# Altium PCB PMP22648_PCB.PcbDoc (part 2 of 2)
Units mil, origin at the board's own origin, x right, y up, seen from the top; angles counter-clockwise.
Board outline 3299.21 x 2751.97 mil, 6 copper layers (Top Layer, GND, GND (Mid2), Signal Layer 3, GND (Mid4), Bottom Layer), stack 107.669 mil thick; 130 components, 60 nets, 290 pads, 212 vias.
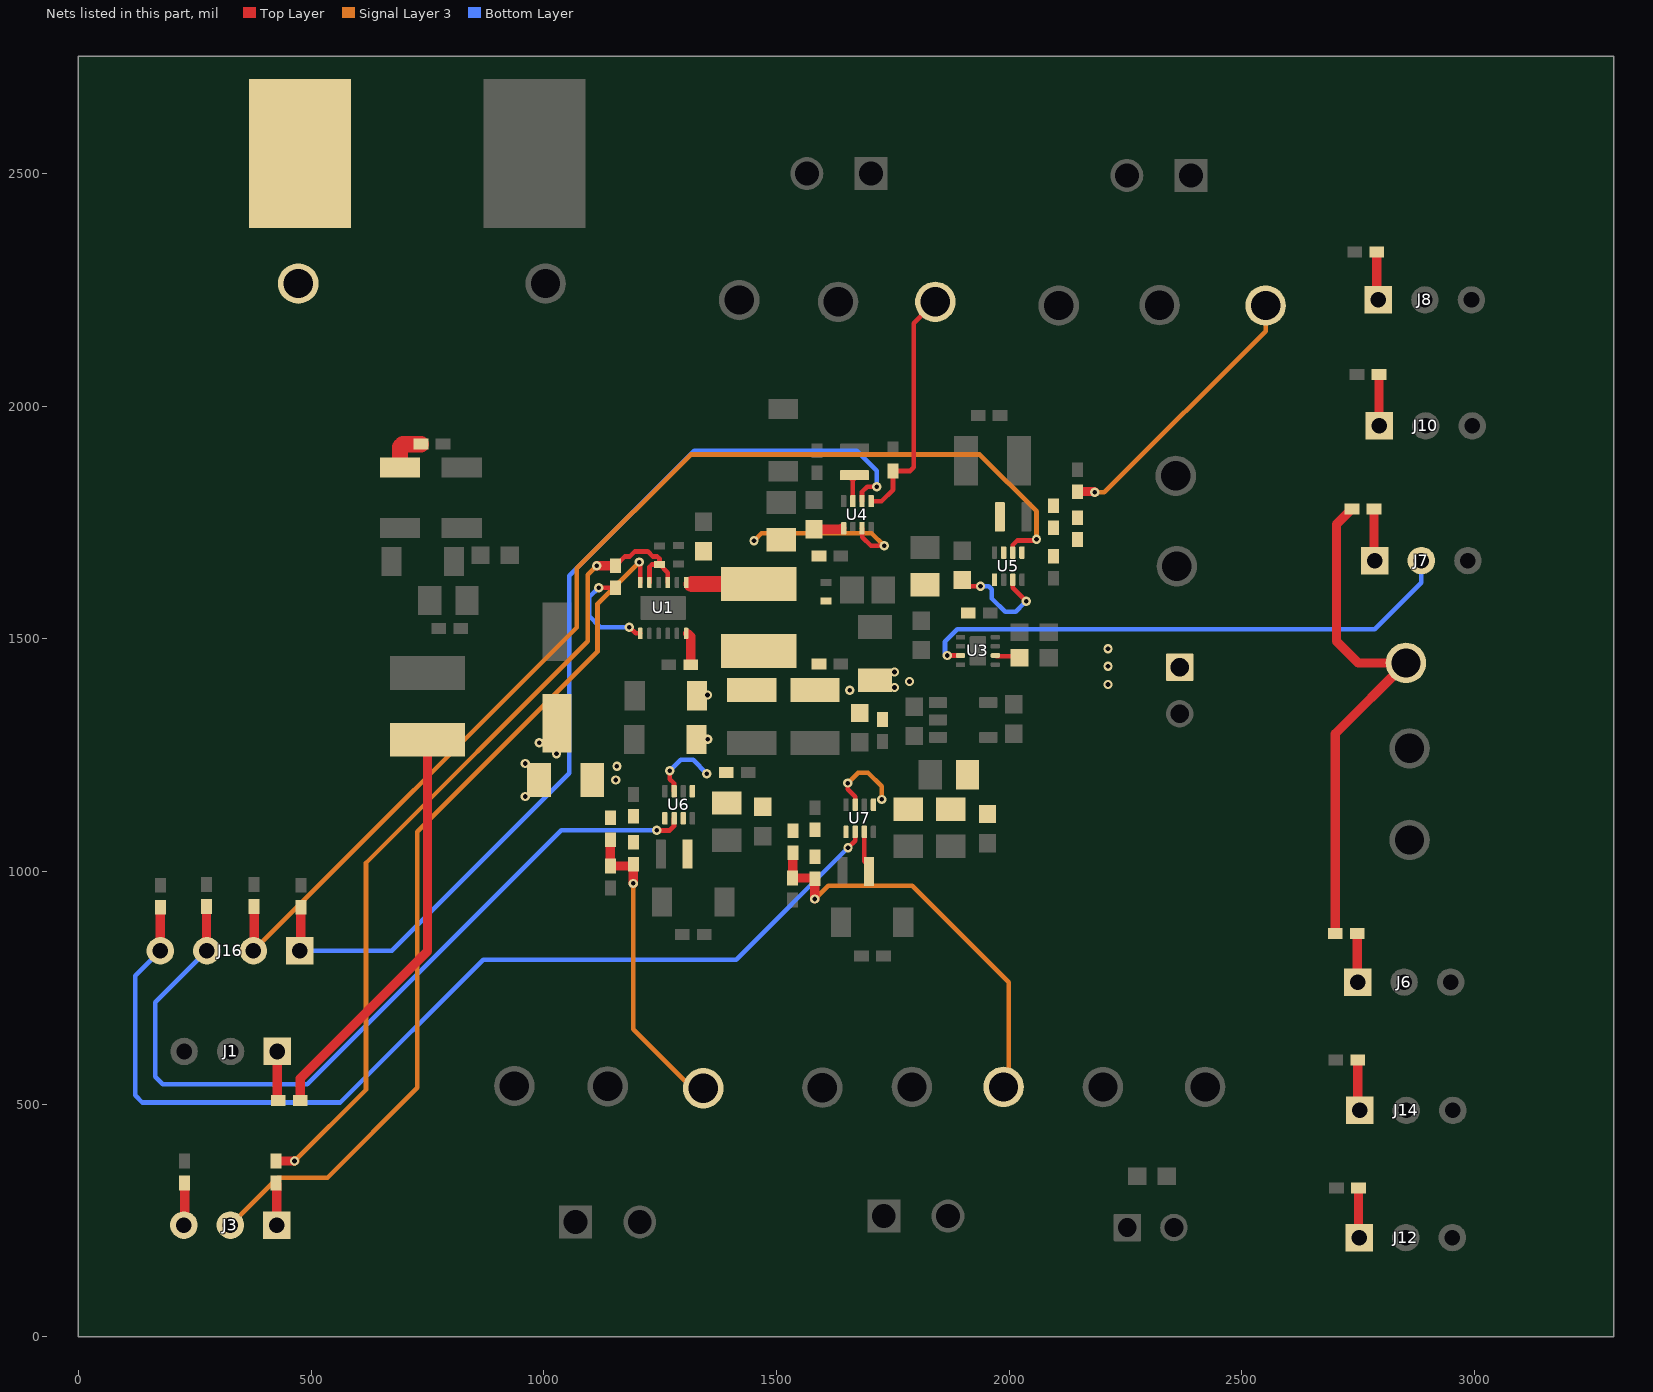
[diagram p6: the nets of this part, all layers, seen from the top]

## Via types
v1: diameter 20, hole 10, Top Layer to Bottom Layer, 207 vias
v2: diameter 19.68, hole 7.87, Top Layer to Bottom Layer, 5 vias

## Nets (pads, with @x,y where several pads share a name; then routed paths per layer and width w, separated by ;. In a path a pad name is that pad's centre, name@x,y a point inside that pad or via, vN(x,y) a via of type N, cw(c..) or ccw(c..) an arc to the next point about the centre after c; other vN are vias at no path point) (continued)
NetC19_1: C19.1 C22.1 R14.2 U4.1 U4.3 | length 432.3
  Top Layer w10: U4.3@1683.99,1737.97 1684.89,1737.07 1684.89,1718.61 1703.37,1700.13 v1(1731.6,1700.13)
  Top Layer w20: C22.1@1580.81,1735.61 1638.16,1735.61 U4.1@1640.52,1737.97
  Signal Layer 3 w10: v1(1452.03,1711.32) 1468.03,1727.32 1704.41,1727.32 v1(1731.6,1700.13)
NetC21_1: C21.1 C27.1 R18.2 U5.1 U5.3 | length 244.7
  Top Layer w10: C27.1@1899.82,1626.78 1913.6,1613 v1(1938.75,1613) ; U5.3@2008.09,1627.17 2008.09,1610.47 v1(2037.21,1581.35)
  Bottom Layer w10: v1(1938.75,1613) 1956.68,1613 1963.11,1606.56 1963.11,1586.92 1991.56,1558.48 2014.34,1558.48 2016.5,1560.64 2016.5,1560.96 2029.9,1574.36 2030.22,1574.36 v1(2037.21,1581.35)
NetC23_1: C23.1 U3.6 | length 55.8
  Top Layer w10: U3.6@1970.47,1464.41 1972.28,1462.6 2022.3,1462.6 C23.1@2022.3,1459.38
NetC25_1: C25.1 C33.1 R24.2 U6.1 U6.3 | length 149.4
  Top Layer w10: v1(1270.58,1216.54) 1270.58,1198.92 1280.14,1189.36 U6.3@1280.14,1172.88
  Bottom Layer w10: v1(1270.58,1216.54) 1294.2,1240.16 1320.9,1240.16 v1(1350.39,1210.66)
NetC29_1: C29.1 C31.1 C38.1 R30.2 U7.1 U7.3 | length 175.5
  Top Layer w10: v1(1653.2,1190.27) 1653.2,1176.8 1669.29,1160.71 U7.3@1669.29,1143.75
  Signal Layer 3 w10: v1(1653.2,1190.27) 1653.27,1190.27 1675.47,1212.47 1696.86,1212.47 1726.27,1183.07 v1(1726.27,1155.18)
NetC30_1: C30.1 R19.1 R22.2 TP7.1 | length 603.9
  Top Layer w20: R19.1@2146.7,1816.68 2182.54,1816.68 v1(2184.26,1814.96)
  Signal Layer 3 w10: v1(2184.26,1814.96) 2204.72,1814.96 2551.31,2161.54 TP7.1@2551.31,2216.54
NetC30_2: C30.2 R22.1 R23.2 U5.5
NetC36_1: C36.1 R25.1 R28.2 TP10.1 | length 664.6
  Top Layer w20: C36.1@1143.07,1068.21 R25.1@1143.07,1012.11 1188.86,1012.11 R28.2@1192.54,1015.8 v1(1192.54,974.71)
  Signal Layer 3 w10: v1(1192.54,974.71) 1192.54,660.95 1318.9,534.59 TP10.1@1342.8,534.59
NetC36_2: C36.2 R28.1 R29.2 U6.5
NetC42_1: C42.1 R31.1 R34.2 TP13.1 | length 889.9
  Top Layer w10: R31.1@1535.15,986.36 R31.1@1535.24,986.46
  Top Layer w20: R31.1@1535.15,986.36 1580.85,986.36 R34.2@1582.67,984.53 v1(1582.68,941.08) ; R31.1@1535.24,986.46 C42.1@1535.24,1040.33
  Signal Layer 3 w10: v1(1582.68,941.08) 1611.41,969.82 1791.77,969.82 1999.55,762.04 1999.55,548.76 TP13.1@1988.19,537.4
NetC42_2: C42.2 R34.1 R35.2 U7.5
NetJ1_1: J1.1 R2.1 | length 106.3
  Top Layer w20: J1.1@427.16,613.55 427.16,510.6 R2.1@429.52,508.23
NetJ3_1: J3.1 R6.2 | length 91.3
  Top Layer w20: R6.2@425.2,331.04 426.69,329.55 J3.1@426.69,240.33
NetJ3_3: J3.3 R7.2 | length 91.4
  Top Layer w20: J3.3@226.69,240.33 228.35,241.99 R7.2@228.35,331.04
NetJ6_1: J6.1 R9.2 | length 104.8
  Top Layer w20: R9.2@2748.03,867.09 2748.03,763.56 J6.1@2748.93,762.65
NetJ7_1: J7.1 R13.2 | length 111.9
  Top Layer w20: R13.2@2784.17,1779.53 2784.17,1670.12 J7.1@2785.94,1668.34
NetJ8_1: J8.1 R15.2 | length 104.7
  Top Layer w20: R15.2@2790.25,2331.81 2790.25,2231.9 J8.1@2793.65,2228.51
NetJ10_1: J10.1 R20.2 | length 110.5
  Top Layer w20: R20.2@2794.82,2068.08 2794.82,1958.29 J10.1@2795.32,1957.78
NetJ12_1: J12.1 R26.2 | length 107.3
  Top Layer w20: R26.2@2750.82,320.23 2750.82,215.46 J12.1@2752.59,213.69
NetJ14_1: J14.1 R32.2 | length 110.5
  Top Layer w20: R32.2@2749.04,595.59 2749.04,491.55 J14.1@2753.64,486.95
NetL5_1: L5.1 U4.7 | length 57.2
  Top Layer w10: U4.7@1664.3,1796.24 L5.1@1664.3,1848.18
  Top Layer w20: L5.1@1664.3,1848.18 L5.1@1668.06,1851.93
NetL6_1: L6.1 U5.7
NetL7_1: L7.1 U6.7
NetL8_1: L8.1 U7.7 | length 75.9
  Top Layer w10: U7.7@1688.97,1085.48 1688.97,1022.1 L8.1@1697.83,1013.24
NetR16_1: R16.1 TP5.1 U4.5 | length 519.5
  Top Layer w10: U4.5@1703.67,1796.24 1725.92,1796.24 1750.74,1821.06 R16.1@1750.74,1860.79 1786.97,1860.79 1795.28,1869.09 1795.28,2178.14 TP5.1@1841.54,2224.41
ON_LS: J7.2 U3.3 | length 1184
  Top Layer w10: v1(1866.91,1464.49) U3.3@1895.67,1464.49
  Bottom Layer w10: v1(1866.91,1464.49) 1862.2,1469.19 1862.2,1493.85 1888.86,1520.51 2785.8,1520.51 2885.94,1620.65 J7.2@2885.94,1668.34
PG_1V8: J16.1 R17.1 U4.6 | length 2135.5
  Top Layer w10: J16.1@476.17,829.94 J16.1@478.15,831.91 ; U4.6@1683.99,1796.24 1683.99,1816.07 1695.01,1827.09 v1(1715.85,1827.09)
  Top Layer w20: J16.1@478.15,831.91 R17.1@478.15,923.23
  Bottom Layer w10: J16.1@476.17,829.94 673.92,829.94 1055.12,1211.13 1055.12,1635.72 1323.5,1904.1 1672.75,1904.1 1715.85,1861 v1(1715.85,1827.09)
PG_1V35: J16.3 R27.1 U6.6 | length 1780
  Top Layer w10: J16.3@275.59,830.52 J16.3@276.17,829.94 ; v1(1243.02,1088.63) 1243.1,1088.55 1270.55,1088.55 1280.14,1098.14 U6.6@1280.14,1114.62
  Top Layer w20: J16.3@275.59,830.52 R27.1@275.59,925.2
  Bottom Layer w10: J16.3@276.17,829.94 165.35,719.12 165.35,559.06 181.1,543.31 492.13,543.31 1037.45,1088.63 v1(1243.02,1088.63)
PG_1V175: J16.4 R33.1 U7.6 | length 2231.9
  Top Layer w10: v1(1653.96,1051.23) 1669.29,1066.55 U7.6@1669.29,1085.48
  Top Layer w20: J16.4@176.17,829.94 176.17,922.72 R33.1@176.69,923.23
  Bottom Layer w10: J16.4@176.17,829.94 122.05,775.81 122.05,519.69 137.8,503.94 562.99,503.94 870.08,811.02 1413.76,811.02 v1(1653.96,1051.23)
PG_3V3_Buck: J16.2 R21.1 U5.6 | length 2477.7
  Top Layer w10: U5.6@2008.09,1685.44 2008.09,1701.92 2017.68,1711.5 2056.01,1711.5 v1(2059.06,1714.55)
  Top Layer w20: J16.2@376.17,829.94 377.95,831.72 R21.1@377.95,925.2
  Signal Layer 3 w10: J16.2@376.17,829.94 1070.87,1524.63 1070.87,1651.47 1315.62,1896.22 1937.04,1896.22 2059.06,1774.21 v1(2059.06,1714.55)
RES: R8.1 U1.7 | length 230.9
  Top Layer w10: v1(1118.04,1610.24) 1118.35,1609.93 R8.1@1154.43,1609.93 ; v1(1184.04,1525.35) 1197.5,1511.9 U1.7@1207.58,1511.9
  Bottom Layer w10: v1(1118.04,1610.24) 1097.92,1590.12 1097.92,1549.31 1121.88,1525.35 v1(1184.04,1525.35)
SW_5V: C1.2 C4.2 L3.1 U1.1 | length 148.7
  Top Layer w35: 1318.31,1618 L3.1@1462.23,1618 L3.1@1458.88,1621.35
SYNC: J3.2 U1.6 | length 1895.9
  Top Layer w10: v1(1205.61,1665.17) 1207.58,1663.2 U1.6@1207.58,1621.35
  Signal Layer 3 w10: J3.2@326.69,240.33 428.87,342.52 535.43,342.52 728.35,535.43 728.35,1085.77 1115.74,1473.16 1115.74,1575.29 v1(1205.61,1665.17)
VBAT: C5.1 J2.1 L2.1 VBAT.1 | length 91.7
  Top Layer w35: L2.1@691.03,1868.41 691.03,1912.38 697.08,1918.43 C5.1@736.24,1918.43
VCC: C14.1 R6.1 R8.2 U1.3 U1.5 | length 1857.4
  Top Layer w10: v1(1114.17,1657.48) v1@1114.48,1657.17 ; R8.2@1154.43,1657.17 1174.43,1677.17 1185.26,1677.17 1196.13,1688.04 1223.19,1688.04 1234.06,1677.17 1243.94,1677.17 1248.92,1672.18 C14.1@1248.92,1660.01 ; U1.5@1227.26,1621.35 1227.26,1654.61 1232.66,1660.01 C14.1@1248.92,1660.01 ; U1.3@1266.63,1621.35 1266.63,1642.3 C14.1@1248.92,1660.01
  Top Layer w20: R6.1@425.2,378.29 v1(464.57,378.29) ; v1@1114.48,1657.17 R8.2@1154.43,1657.17
  Signal Layer 3 w10: v1@464.9,378.29 618.11,531.5 618.11,1018.62 1094.49,1495 1094.49,1637.8 v1(1114.17,1657.48)
  Signal Layer 3 w20: v1(464.57,378.29) v1@464.9,378.29
VIN_5V: C7.1 C9.1 C10.1 R10.2 U1.12 | length 70.1
  Top Layer w20: U1.12@1309.11,1511.9 1315.85,1505.16 C10.1@1315.85,1444.57
  other v1: 1155.06,1196.85 1157.33,1226.6 1352.34,1284.81 1351.94,1379.52
VIN_FILT: C8.1 L1.2 R2.2 R10.1 | length 888.4
  Top Layer w20: R2.2@476.77,508.23 476.77,555.51 750.34,829.08 L1.2@750.34,1283.36
  other v1: 960.63,1161.42 960.63,1232.21 1027.56,1253.02 990.16,1277
VSYS_5V: C11.1 C12.1 C17.1 J4.1 L3.2 R5.2 R9.1 R11.1 R12.1 R13.1 TP2.1 | length 1110.8
  Top Layer w20: R9.1@2700.79,867.09 2700.79,1296.41 TP2.1@2852.78,1448.41 2750.51,1448.41 2703.77,1495.15 2703.77,1746.37 R13.1@2736.92,1779.53
  other v1: 1657.88,1389.76 1753.67,1395.68 2212.6,1402.28 1786.07,1408.6 1753.67,1428.92 2212.6,1441.58 2212.6,1479.03
pads on no net: U3.0

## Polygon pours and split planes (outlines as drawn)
NetC13_1 on Top Layer "TOP_LAYER_NETC13_1_P110" (solid, remove dead copper, pour order 110): 1773.69,1379.52 1862.2,1379.52 1862.2,1350.39 1860.71,1350.39 1818.61,1350.39 1818.61,1330.71 1773.69,1330.71
GND on Top Layer "TOP_LAYER_GND_P108" (solid, remove dead copper, pour order 108): 1330.71,2751.97 1330.71,2145.67 2240.16,2145.67 2244.09,2141.73 2244.09,732.28 886.14,732.28 887.37,733.51 887.37,1203.27 615.62,1203.27 614.17,1204.72 614.17,1416.43 475.31,1416.43 476.61,1417.72 476.61,1849.65 118.11,1849.65 118.11,2751.97
3.3V_LDO on Top Layer "TOP_LAYER_3.3V_LDO_P106" (solid, remove dead copper, pour order 106): 1944.73,1381.72 1944.09,1381.09 1944.09,1339.68 2027.96,1339.68 2029.06,1338.58 2029.9,1339.42 2029.9,1381.57
VIN_5V on Top Layer "TOP_LAYER_VIN_5V_P088" (solid, remove dead copper, pour order 88): 1075.08,1242.2 1074.8,1150.59 1164.87,1150.59 1169.29,1150.59 1169.29,1243.53
NetC21_1 on Top Layer "TOP_LAYER_NETC21_1_P062" (solid, remove dead copper, pour order 62): 1779.19,1582.31 1885.46,1582.31 1885.83,1582.68 1886.47,1582.03 1886.47,1543.31 1928.42,1543.31 1929.13,1544.02 1928.36,1544.79 1928.36,1604.03 1963.11,1604.03 1974.22,1615.13 1974.22,1640.5 1929.59,1640.5 1929.59,1649.61 1779.19,1649.61
NetC30_2 on Top Layer "TOP_LAYER_NETC30_2_P060" (solid, remove dead copper, pour order 60): 2021.67,1673.23 2073.86,1673.23 2073.86,1657.48 2118.11,1657.17 2118.11,1688.04 2117.17,1688.98 2167.2,1689.19 2167.2,1731.13 2165.35,1732.28 2117.17,1732.28 2117.17,1755.91 2073.86,1755.91 2073.86,1696.85 2073.32,1696.31 2022.3,1696.31
NetC19_1 on Top Layer "TOP_LAYER_NETC19_1_P058" (solid, remove dead copper, pour order 58): 1437.59,1753.5 1437.41,1679.33 1550.58,1679.33 1552.26,1681.01 1552.26,1706.08 1567.06,1706.08 1567.06,1666.09 1610.24,1666.09 1609.35,1723.41 1649.54,1723.41 1648.93,1724.02 1648.93,1753.5
NetC16_1 on Top Layer "TOP_LAYER_NETC16_1_P056" (solid, remove dead copper, pour order 56): 1673.23,1565.84 1673.23,1444.84 1782.48,1444.92 1782.48,1434.35 1783.83,1432.99 1905.51,1432.99 1905.09,1447.59 1900.09,1447.59 1838.22,1447.59 1838.22,1481.54 1907.5,1481.54 1907.5,1511.27 1903.03,1515.75 1832.6,1515.75 1760.41,1515.75 1760.41,1565.84
VSYS_5V on Top Layer "TOP_LAYER_VSYS_5V_P052" (solid, remove dead copper, pour order 52): 1361.83,1527.56 1568.25,1527.56 1568.25,1467.45 1610.24,1467.41 1610.24,1424.11 1664.28,1424.11 1664.28,1444.88 1795.28,1444.88 1795.28,1370.37 1751.87,1370.37 1751.87,1309.34 1750.19,1311.02 1651.48,1311.02 1651.48,1342.89 1651.93,1343.34 1651.48,1343.79 1361.83,1343.79
NetC29_1 on Top Layer "TOP_LAYER_NETC29_1_P050" (solid, remove dead copper, pour order 50): 1700.79,1168.3 1743.46,1168.3 1875,1168.3 1874.02,1169.28 1874.02,1248.35 1944.85,1248.35 1944.88,1153.35 1979.96,1153.35 1982.28,1151.04 1982.28,1102.36 1743.46,1102.36 1743.46,1134.3 1742.09,1132.92 1700.79,1132.92
NetC36_2 on Top Layer "TOP_LAYER_NETC36_2_P048" (solid, remove dead copper, pour order 48): 1122.57,1139.84 1123.93,1138.47 1266.63,1138.47 1266.63,1107.64 1265.29,1106.3 1214.2,1106.3 1214.2,1043.31 1213.51,1042.62 1164.72,1042.62 1164.72,1094.49 1121.41,1094.49
NetC25_1 on Top Layer "TOP_LAYER_NETC25_1_P044" (solid, remove dead copper, pour order 44): 1310.57,1189.6 1340.23,1189.6 1340.23,1234.3 1417.32,1234.3 1417.32,1181.33 1498.77,1181.33 1499.27,1180.83 1499.27,1114.17 1353.33,1114.17 1353.33,1157.48 1310.6,1157.48
VIN_FILT on Top Layer "TOP_LAYER_VIN_FILT_P042" (solid, remove dead copper, pour order 42): 649.97,1355.21 650.85,1354.33 893.7,1354.33 893.7,1387.65 896.9,1390.85 897.98,1389.76 1162.31,1389.76 1162.31,1243.11 1039.37,1243.11 1039.37,1150.91 824.31,1150.62 824.31,1224.41 646.01,1224.41
NetC42_2 on Top Layer "TOP_LAYER_NETC42_2_P032" (solid, remove dead copper, pour order 32): 1514.74,1111.95 1518.72,1107.98 1656.21,1107.98 1656.21,1064.42 1604.33,1064.25 1604.33,1008.15 1556.8,1007.87 1556.8,1070.77 1513.59,1070.87
NetL8_1 on Top Layer "TOP_LAYER_NETL8_1_P030" (solid, remove dead copper, pour order 30): 1681.55,1092.65 1681.55,958.96 1713.58,958.96 1713.58,1035.42 1700.79,1035.44 1700.79,1092.56
5V_LS on Top Layer "TOP_LAYER_5V_LS_P024" (solid, remove dead copper, pour order 24): 1935.69,1577.68 1935.69,1534.37 1952.76,1534.37 1952.76,1478.27 1988.59,1478.27 1992.77,1474.09 1993.81,1475.13 1993.81,1487.64 2062.79,1487.64 2063.19,1565.54 2017.25,1565.54 1984.9,1533.19 1984.9,1576.79
NetC30_1 on Top Layer "TOP_LAYER_NETC30_1_P022" (solid, remove dead copper, pour order 22): 2073.86,1811.76 2073.86,1763.78 2124.6,1763.78 2126.2,1762.19 2125.04,1761.03 2125.04,1732.28 2168.35,1732.28 2168.35,1834.65 2125.04,1834.65 2125.04,1811.02
VIN_5V on Top Layer "TOP_LAYER_VIN_5V_P010" (solid, remove dead copper, pour order 10): 1275.43,1557.75 1275.22,1236.22 1356.91,1236.22 1356.91,1425.2 1341.35,1425.2 1340.23,1424.07 1338.58,1425.72 1338.58,1558.54
SW_5V on Top Layer "TOP_LAYER_SW_5V_P006" (solid, remove dead copper, pour order 6): 1295.28,1645.37 1314.96,1645.37 1314.87,1712.6 1371.95,1712.6 1370.68,1711.32 1370.68,1660.18 1623.95,1660.18 1623.95,1570.87 1566.56,1570.87 1357.9,1570.87 1357.9,1606.3 1294.54,1605.36
GND on Bottom Layer "BOTTOM_LAYER_GND_P098" (solid, remove dead copper, pour order 98): 1330.71,2751.97 1330.71,2145.67 2240.16,2145.67 2244.09,2141.73 2244.09,732.28 886.14,732.28 887.37,733.51 887.37,1203.27 615.62,1203.27 614.17,1204.72 614.17,1416.43 475.31,1416.43 476.61,1417.72 476.61,1849.65 118.11,1849.65 118.11,2751.97
VSYS_5V on Bottom Layer "BOTTOM_LAYER_VSYS_5V_P068" (solid, remove dead copper, pour order 68): 1361.83,1531.5 2228.35,1531.5 2228.35,1377.64 1646.32,1377.64 1646.01,1342.52 1363.11,1342.52 1361.83,1343.79
GND on Signal Layer 3 "SIGNAL_LAYER_3_GND_P094" (solid, remove dead copper, pour order 94): 1330.71,2751.97 1330.71,2145.67 2240.16,2145.67 2244.09,2141.73 2244.09,732.28 886.14,732.28 887.37,733.51 887.37,1203.27 615.62,1203.27 614.17,1204.72 614.17,1416.43 475.31,1416.43 476.61,1417.72 476.61,1849.65 118.11,1849.65 118.11,2751.97
VIN_5V on Signal Layer 3 "SIGNAL_LAYER_3_VIN_5V_P072" (solid, remove dead copper, pour order 72): 1288.28,1523.62 1184.04,1397.18 1075.15,1263.78 1074.8,1150.59 1160.16,1150.59 1161.15,1149.61 1161.15,1194.76 1251.97,1194.76 1251.97,1228.35 1384.2,1228.35 1384.2,1523.62
5V_LS on Signal Layer 3 "SIGNAL_LAYER_3_5V_LS_P070" (solid, remove dead copper, pour order 70): 1417.32,1692 1417.32,1165.98 1858.27,1165.98 1858.27,1468.26 2075.02,1468.26 2075.02,1686.27
GND on GND "GND_GND_P092" (solid, remove dead copper, pour order 92): 1330.71,2751.97 1330.71,2145.67 2240.16,2145.67 2244.09,2141.73 2244.09,732.28 886.14,732.28 887.37,733.51 887.37,1203.27 615.62,1203.27 614.17,1204.72 614.17,1416.43 475.31,1416.43 476.61,1417.72 476.61,1849.65 118.11,1849.65 118.11,2751.97
GND on GND (Mid2) "GND_GND_P100" (solid, remove dead copper, pour order 100): 1330.71,2751.97 1330.71,2145.67 2240.16,2145.67 2244.09,2141.73 2244.09,732.28 886.14,732.28 887.37,733.51 887.37,1203.27 615.62,1203.27 614.17,1204.72 614.17,1416.43 475.31,1416.43 476.61,1417.72 476.61,1849.65 118.11,1849.65 118.11,2751.97
GND on GND (Mid4) "GND_GND_P096" (solid, remove dead copper, pour order 96): 1330.71,2751.97 1330.71,2145.67 2240.16,2145.67 2244.09,2141.73 2244.09,732.28 886.14,732.28 887.37,733.51 887.37,1203.27 615.62,1203.27 614.17,1204.72 614.17,1416.43 475.31,1416.43 476.61,1417.72 476.61,1849.65 118.11,1849.65 118.11,2751.97

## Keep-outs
Keep-Out Layer:
  text ".Layer_Name" at 577,-858.49 h60

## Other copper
Top Layer:
  region net 1V35: 1121.41,984.25 1164.72,984.25 1164.72,953.14 1163.57,951.99 1165.51,950.05 1231.2,950.05 1231.2,1020.3 1241.16,1020.3 1241.16,1066.38 1243.02,1068.24 1262.77,1067.96 1262.77,1020.3 1286.05,1020.3 1286.05,887.99 1287.4,886.63 1299.21,886.63 1299.21,791.18 1297.92,789.89 1019.68,789.89 1019.68,331.84 1021.97,329.55 1123.93,329.55 1123.93,40.97 1125.98,38.92 1124.24,37.18 850.39,37.18 850.39,700.79 1121.41,971.81
  pour cut-out: 212.6,2751.97 212.6,1940.95 566.93,1940.94 566.93,1492.13 842.52,1492.13 853.11,1492.13 883.43,1522.45 883.43,1556.9 967.27,1556.9 985.17,1574.8 984.25,1575.73 984.25,1966.76 1220.47,1966.76 1220.47,2751.97
  region net CGND: 826.77,2708.66 826.77,1968.5 784.86,1968.5 784.86,1847.37 877.32,1847.37 881.89,1851.93 883.43,1850.39 944.88,1850.39 944.88,2125.14 1143.07,2125.14 1143.07,2708.66
  region net VBAT: 315.4,2704.72 314.96,2086.61 315.41,2087.07 629.92,2087.07 629.92,1846.46 746.15,1846.46 746.15,2320.78 744.09,2322.83 633.86,2322.83 633.86,2704.72
  region net 3V3_Buck: 2322.83,2716.17 2322.83,2377.95 2208.66,2263.78 2208.66,2125.98 2114.17,2031.5 1964.57,2031.5 1964.57,1963.15 1964.57,1952.76 1978.75,1951.34 1978.75,1820.23 2013.04,1820.23 2013.04,1735.61 2073.86,1735.61 2073.86,1846.03 2173.23,1846.03 2173.23,1895.8 2442.91,2165.49 2442.91,2714.57
  region net 1V175: 1513.49,953.74 1513.49,38.92 1516.98,35.43 1788.91,35.43 1788.91,346.33 1787.07,344.49 1692.91,344.49 1692.91,870.08 1692.91,874.02 1660.43,874.02 1660.43,1032.56 1611.73,1032.56 1611.73,917.32 1556.8,917.32 1556.8,954.72 1549.04,954.72
  region net 3.3V_LDO: 2122.05,617.24 2126.91,612.38 2126.91,39.37 2291.34,39.37 2291.34,618.04
  region net 1V8: 1641.73,2712.6 1641.73,2342.52 1639.76,2340.55 1557.08,2340.55 1557.08,2025.58 1555.12,2023.62 1472.44,2023.62 1472.44,1957.43 1480.84,1949.03 1561.02,1949.03 1561.02,1888.3 1770.93,1888.3 1770.93,1932.17 1770.93,1941.82 1703.3,1941.82 1703.3,2432.7 1707.38,2436.78 1767.49,2436.78 1767.49,2708.89 1763.78,2712.6
  region net NetL6_1: 1993.81,1674.2 1983.12,1674.2 1983.12,1721.98 1978.15,1726.94 1965.38,1726.94 1965.38,1797.77 1996.06,1797.77
  region net NetL7_1: 1294.35,1128.52 1302.62,1128.52 1309.01,1073.11 1323.71,1073.11 1323.71,1002.29 1296.85,1002.27
  region net NetL5_1: 1632.63,1866.14 1703.47,1866.14 1703.47,1840.3 1669.16,1840.3 1669.16,1783.46 1659.99,1783.46 1659.99,1830.72 1653.54,1837.17 1632.63,1837.17
  text ".Layer_Name" at 577,-858.49 h60
GND:
  pour cut-out: 212.6,2751.97 212.6,1940.95 566.93,1940.94 566.93,1492.13 842.52,1492.13 853.11,1492.13 883.43,1522.45 883.43,1556.9 967.27,1556.9 985.17,1574.8 984.25,1575.73 984.25,1966.76 1220.47,1966.76 1220.47,2751.97
GND (Mid2):
  pour cut-out: 212.6,2751.97 212.6,1940.95 566.93,1940.94 566.93,1492.13 842.52,1492.13 853.11,1492.13 883.43,1522.45 883.43,1556.9 967.27,1556.9 985.17,1574.8 984.25,1575.73 984.25,1966.76 1220.47,1966.76 1220.47,2751.97
Signal Layer 3:
  pour cut-out: 212.6,2751.97 212.6,1940.95 566.93,1940.94 566.93,1492.13 842.52,1492.13 853.11,1492.13 883.43,1522.45 883.43,1556.9 967.27,1556.9 985.17,1574.8 984.25,1575.73 984.25,1966.76 1220.47,1966.76 1220.47,2751.97
GND (Mid4):
  pour cut-out: 212.6,2751.97 212.6,1940.95 566.93,1940.94 566.93,1492.13 842.52,1492.13 853.11,1492.13 883.43,1522.45 883.43,1556.9 967.27,1556.9 985.17,1574.8 984.25,1575.73 984.25,1966.76 1220.47,1966.76 1220.47,2751.97
Bottom Layer:
  pour cut-out: 212.6,2751.97 212.6,1940.95 566.93,1940.94 566.93,1492.13 842.52,1492.13 853.11,1492.13 883.43,1522.45 883.43,1556.9 967.27,1556.9 985.17,1574.8 984.25,1575.73 984.25,1966.76 1220.47,1966.76 1220.47,2751.97
  region net VSYS_5V: 2201.68,1505.21 2201.68,1377.95 2971.88,1377.95 2971.88,1505.21
  text ".Layer_Name" at 577,-858.49 h60

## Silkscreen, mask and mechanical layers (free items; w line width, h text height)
Top Overlay:
  drawing of 399 lines, arcs and shapes, not listed
  text "Layer" at 5606.87,2892.62 h60
  text "Name" at 6016.78,2892.62 h60
  text "Material" at 6956.52,2892.62 h60
  text "Thickness" at 7816.29,2892.62 h60
  text "Constant" at 8466.13,2892.62 h60
  text "Board Layer Stack" at 9035.99,2892.62 h60
  text "1" at 5606.87,2772.62 h60
  text "Top Overlay" at 6016.78,2772.62 h60
  text "3V3 Buck Rail" at 2212.6,2661.42 h40
  text "1V8 Rail" at 1574.18,2659.45 h40
  text "2" at 5606.87,2652.62 h60
  text "Top Solder" at 6016.78,2652.62 h60
  text "Solder Resist" at 6956.52,2652.62 h60
  text "0.40mil" at 7816.29,2652.62 h60
  text "3.5" at 8466.13,2652.62 h60
  text "3" at 5606.87,2532.62 h60
  text "Top Layer" at 6016.78,2532.62 h60
  text "Copper" at 6956.52,2532.62 h60
  text "1.40mil" at 7816.29,2532.62 h60
  text "OUT" at 1815.94,2488.19 h40
  text "OUT" at 2503.94,2488.19 h40
  text "GND" at 1390.57,2484.25 h40
  text "GND" at 2083.7,2484.25 h40
  text "4" at 5606.87,2412.62 h60
  text "Dielectric 2" at 6016.78,2412.62 h60
  text "10.00mil" at 7816.29,2412.62 h60
  text "4.2" at 8466.13,2412.62 h60
  text "5" at 5606.87,2292.62 h60
  text "GND" at 6016.78,2292.62 h60
  text "Copper" at 6956.52,2292.62 h60
  text "1.42mil" at 7816.29,2292.62 h60
  text "1V8" at 3074.8,2263.78 h40 r270
  text "6" at 5606.87,2172.62 h60
  text "Dielectric 3" at 6016.78,2172.62 h60
  text "10.00mil" at 7816.29,2172.62 h60
  text "4.2" at 8466.13,2172.62 h60
  text "EN" at 2881.27,2161.42 h40 r270
  text "GND" at 2985.94,2161.42 h40 r270
  text "7" at 5606.87,2052.62 h60
  text "GND" at 6016.78,2052.62 h60
  text "Copper" at 6956.52,2052.62 h60
  text "1.42mil" at 7816.29,2052.62 h60
  text "3V3 Buck" at 3074.8,2031.5 h40 r270
  text "Output" at 2456.69,1948.82 h40 r270
  text "Load Switch" at 2492.13,1948.82 h40 r270
  text "8" at 5606.87,1932.62 h60
  text "Dielectric1" at 6016.78,1932.62 h60
  text "FR-4" at 6956.52,1932.62 h60
  text "59.20mil" at 7816.29,1932.62 h60
  text "4.8" at 8466.13,1932.62 h60
  text "GND" at 2982,1885.36 h40 r270
  text "EN" at 2885.2,1881.89 h40 r270
  text "___" at 1367.96,1868.97 h40
  text "__" at 1372.59,1865.34 h40 r270
  text "__" at 1430.1,1864.6 h40 r270
  text "___" at 1367.96,1829.99 h40
  text "____________" at 118.11,1818.9 h40
  text "9" at 5606.87,1812.62 h60
  text "Signal Layer 3" at 6016.78,1812.62 h60
  text "Copper" at 6956.52,1812.62 h60
  text "1.42mil" at 7816.29,1812.62 h60
  text "________________________" at 122.05,1808.78 h40 r270
  text "________________________" at 358.27,1809.22 h40 r270
  text "Load Switch" at 3078.74,1771.65 h40 r270
  text "__" at 1908.18,1768.77 h40 r270
  text "__" at 1964.73,1768.77 h40 r270
  text "___" at 1961.88,1763.17 h40 r180
  text "__" at 1148.25,1741.53 h40 r270
  text "__" at 1205.42,1739.72 h40 r270
  text "___" at 1202.46,1736.22 h40 r180
  text "___" at 1961.88,1725.7 h40 r180
  text "___" at 1202.46,1698.14 h40 r180
  text "10" at 5606.87,1692.62 h60
  text "Dielectric 4" at 6016.78,1692.62 h60
  text "10.00mil" at 7816.29,1692.62 h60
  text "4.2" at 8466.13,1692.62 h60
  text "GND" at 2451.09,1690.22 h40 r270
  text "GND" at 2971.88,1597.65 h40 r270
  text "EN" at 2873.39,1594.49 h40 r270
  text "11" at 5606.87,1572.62 h60
  text "GND" at 6016.78,1572.62 h60
  text "Copper" at 6956.52,1572.62 h60
  text "1.42mil" at 7816.29,1572.62 h60
  text "12" at 5606.87,1452.62 h60
  text "Dielectric 5" at 6016.78,1452.62 h60
  text "10.00mil" at 7816.29,1452.62 h60
  text "4.2" at 8466.13,1452.62 h60
  text "__" at 1828.1,1441.95 h40 r270
  text "__" at 1884.95,1440.94 h40 r270
  text "___" at 1882.25,1436.37 h40 r180
  text "5V Rail" at 2436.04,1426.92 h40
  text "__" at 2053.55,1415.7 h40 r270
  text "__" at 2110.07,1414.72 h40 r270
  text "5V Rail Testpoints" at 3035.94,1413.39 h40 r270
  text "___" at 2107.3,1411.22 h40 r180
  text "___" at 1881.89,1398.09 h40 r180
  text "___" at 2107.23,1371.85 h40 r180
  text "Testpoints:" at 173.23,1342.51 h40 r90
  text "Red - Output voltage" at 224.41,1342.51 h40 r90
  text "Yellow - NWA resistor (Bode)" at 283.46,1342.51 h40 r90
  text "Black - GND" at 340.67,1342.99 h40 r90
  text "____________" at 118.11,1334.65 h40
  text "13" at 5606.87,1332.62 h60
  text "Bottom Layer" at 6016.78,1332.62 h60
  text "Copper" at 6956.52,1332.62 h60
  text "1.40mil" at 7816.29,1332.62 h60
  text "GND" at 2436.66,1322.88 h40
  text "14" at 5606.87,1212.62 h60
  text "Bottom Solder" at 6016.78,1212.62 h60
  text "Solder Resist" at 6956.52,1212.62 h60
  text "0.40mil" at 7816.29,1212.62 h60
  text "3.5" at 8466.13,1212.62 h60
  text "__" at 2002.73,1101.03 h40 r270
  text "__" at 2059.06,1101.38 h40 r270
  text "___" at 2056.02,1096.88 h40 r180
  text "15" at 5606.87,1092.62 h60
  text "Bottom Overlay" at 6016.78,1092.62 h60
  text "PG_1V175" at 190.14,1069.77 h40 r90
  text "PG_1V35" at 291.86,1069.77 h40 r90
  text "PG_3V3_Buck" at 395.8,1065.83 h40 r90
  text "PG_1V8" at 491.86,1065.83 h40 r90
  text "___" at 2056.1,1057.21 h40 r180
  text "__" at 1098.34,1014.29 h40 r270
  text "__" at 1041.59,1013.03 h40 r270
  text "___" at 1095.21,1009.19 h40 r180
  text "___" at 1095.21,969.82 h40 r180
  text "3V3 LDO" at 3035.43,834.65 h40 r270
  text "PG Jumper" at 78.74,751.97 h40 r90
  text "GND" at 2934.87,688.92 h40 r270
  text "EN" at 2834.02,685.04 h40 r270
  text "'.PRJ_Number'.PCB_Rev" at 3161.42,646.09 h108.27 r270
  text "5V" at 127.12,592.84 h40 r90
  text "1V175" at 3035.43,539.37 h40 r270
  text "EN" at 338.58,492.13 h40 r90
  text "GND" at 238.19,466.22 h40 r90
  text "GND" at 2939.58,420.79 h40 r270
  text "3V3 LDO" at 2132.36,415.35 h40
  text "GND" at 2385.83,414.89 h40
  text "EN" at 2837.96,413.39 h40 r270
  text "1V35" at 3043.31,255.91 h40 r270
  text "OUT" at 1543.31,251.97 h40
  text "GND" at 1969.31,251.97 h40
  text "OUT" at 882.78,236.36 h40
  text "GND" at 1303.89,236.36 h40
  text "GND" at 2939.58,141.26 h40 r270
  text "5V Buck MODE" at 136.84,137.96 h40 r90
  text "EN" at 2836.41,137.8 h40 r270
  text "GND" at 2358.27,125.98 h40
  text "3V3 LDO" at 2146.68,122.05 h40
  text "AUTO" at 235.26,55.28 h40 r90
  text "SYNC" at 337.62,55.28 h40 r90
  text "1V175 Rail" at 1747.41,53.15 h40
  text "FPWM" at 443.92,47.41 h40 r90
  text "1V35 Rail" at 1063.88,47.39 h40
  text ".Layer_Name" at 577,-858.49 h60
Bottom Overlay:
  text ".Layer_Name" at 577,-858.49 h60
Top Paste:
  text ".Layer_Name" at 577,-858.49 h60
Bottom Paste:
  text ".Layer_Name" at 577,-858.49 h60
Top Solder:
  pour cut-out: 1205.68,1593.98 1307.7,1593.98 1307.97,1593.71 1307.97,1539.26 1205.72,1539.26
  text ".Layer_Name" at 577,-858.49 h60
  text ".Layer_Name" at 577,-858.49 h60
Bottom Solder:
  text ".Layer_Name" at 577,-858.49 h60
Drill Guide:
  text ".Layer_Name" at 577,-858.49 h60
M1 Board Outline:
  the board outline again, w10
  text ".Layer_Name" at 577,-858.49 h60
M2 Board Dimensions:
  rectangle: 0,-275 125,-150
  rectangle: 125,-400 500,-275
  lines w7: 0,-275 1000,-275 ; 125,-400 125,-150 ; 250,-400 250,-150 ; 500,-400 500,-150 ; 750,-400 750,-150 ; 0,-400 1000,-400 1000,-150 0,-150 0,-400
  text ".Layer_Name" at 577,-858.49 h60
M3 3D STEP Top:
  text ".Layer_Name" at 577,-858.49 h60
M4 3D STEP Bottom:
  text ".Layer_Name" at 577,-858.49 h60
M5 Assembly Top:
  lines w10: -292,-930.17 6308,-930.17 ; -292,-726.83 6310,-726.83 ; -292,-523.5 -292,-1133.5 3713,-1133.5 6310,-1133.5 6310,-523.5 -291.5,-523.5 -291.5,-1133.5 1284,-1133.5 ; 2173,-1133.5 2173,-523.5 ; 3440,-726.83 3440,-523.5 ; 4280,-726.83 4280,-523.5 ; 4902,-1140 4902,-937.17
  text "COMPONENTS MARKED 'DNP' SHOULD NOT BE POPULATED." at 1153.5,-318.5 h60
  text "ASSEMBLY VARIANT:" at 1153,-434 h60
  text ".VariantName" at 2189,-434 h60
  text "PCB VIEWED FROM TOP SIDE" at -228.5,-655.67 h60
  text "BOARD #:" at 2248,-655.67 h60
  text ".PRJ_Number" at 2793.5,-655.67 h60
  text "REV:" at 3638,-655.67 h60
  text ".PCB_Rev" at 3929.5,-655.67 h60
  text "SVN REV:" at 4476,-655.67 h60
  text ".VersionControl_RevNumber" at 4982,-655.67 h60
  text "TID #:" at 2248,-859 h60
  text ".TID" at 2793.5,-859 h60
  text "PLOT NAME =" at -228.5,-1064.34 h60
  text ".plot_File_Name" at 577,-1064.34 h60
  text "GENERATED    :" at 2250,-1064.34 h60
  text ".Print_Date" at 3119.5,-1064.34 h60
  text ".Print_Time" at 3848.5,-1064.34 h60
  text "TEXAS INSTRUMENTS" at 5113,-1064.34 h60
M6 Assembly Bottom:
  lines w10: -292.5,-727.33 6309.5,-727.33 ; -290.5,-930.67 6309.5,-930.67 ; 1115.5,-1140.5 1115.5,-937.67 ; 1737.5,-727.33 1737.5,-524 ; 2577.5,-727.33 2577.5,-524 ; 3844.5,-1134 3844.5,-524 ; 4733.5,-1134 6309,-1134 6309,-524 -292.5,-524 -292.5,-1134 2304.5,-1134 6309.5,-1134 6309.5,-524
  text "COMPONENTS MARKED 'DNP' SHOULD NOT BE POPULATED." at 6102,-318 h60
  text ".VariantName" at 5058,-434 h60
  text "ASSEMBLY VARIANT:" at 6097,-434 h60
  text ".VersionControl_RevNumber" at 1035.5,-656.17 h60
  text "SVN REV:" at 1541.5,-656.17 h60
  text ".PCB_Rev" at 2088,-656.17 h60
  text "REV:" at 2379.5,-656.17 h60
  text ".PRJ_Number" at 3224,-656.17 h60
  text "BOARD #:" at 3769.5,-656.17 h60
  text "PCB VIEWED FROM BOTTOM SIDE" at 6246,-656.17 h60
  text ".TID" at 3224,-859.5 h60
  text "TID #:" at 3769.5,-859.5 h60
  text "TEXAS INSTRUMENTS" at 904.5,-1064.84 h60
  text ".Print_Time" at 2169,-1064.84 h60
  text ".Print_Date" at 2898,-1064.84 h60
  text "GENERATED    :" at 3767.5,-1064.84 h60
  text ".plot_File_Name" at 5440.5,-1064.84 h60
  text "PLOT NAME =" at 6246,-1064.84 h60
M9 Title Sheet:
  drawing of 57 lines, arcs and shapes, not listed
  text "1" at 739.84,8036.5 h70
  text "2" at 3235.5,8036.5 h70
  text "3" at 5724.84,8036.5 h70
  text "4" at 8231.51,8036.5 h70
  text "5" at 10730.5,8036.5 h70
  text "6" at 13235.5,8036.5 h70
  text "A" at -416.5,6893.5 h70
  text "A" at 14383.5,6893.5 h70
  text "B" at -416.5,4513.5 h70
  text "B" at 14383.5,4513.5 h70
  text "C" at -416.5,2138.5 h70
  text "C" at 14383.5,2138.5 h70
  text "PROJECT TITLE:" at 11343.5,277.5 h45
  text ".PRJ_Title" at 11393.5,144.17 h70
  text "DESIGNED FOR:" at 11343.5,-23.5 h45
  text ".PRJ_Customer" at 11393.5,-163.5 h70
  text "D" at -416.5,-231.5 h70
  text "D" at 14383.5,-231.5 h70
  text "FILE NAME:" at 11343.5,-323.5 h45
  text ".PCB_File_Name_No_Path" at 11393.5,-443.5 h70
  text "Texas Instruments (TI) and/or its licensors do not warrant the accuracy or completeness of this specification" at 6374,-605.34 h45
  text "ENGINEER:" at 11343.5,-613.5 h45
  text "LAYOUT BY:" at 12848.5,-613.5 h45
  text "or any information contained therein. TI and/or its licensors do not warrant that this design will meet" at 6329.01,-718 h45
  text ".PRJ_Engineer" at 11393.5,-768.49 h70
  text ".PCB_Layout" at 12899,-768.49 h70
  text "the specifications, will be suitable for your application or fit for any particular purpose, or will operate in" at 6329.01,-830.67 h45
  text ".Layer_Name" at 577,-858.49 h60
  text "ALTIUM DESIGNER VERSION:" at 12848.5,-923.5 h45
  text "an implementation. TI and/or its licensors do not warrant that the design is production worthy. You should" at 6329.01,-943.33 h45
  text "completely validate and test your design implementation to confirm the system functionality for your application." at 6374,-1056 h45
  text ".print_Scale" at 11393.5,-1056.83 h70
  text ".Application_BuildNumber" at 12899,-1056.83 h70
  text "1" at 739.84,-1263.5 h70
  text "2" at 3235.5,-1263.5 h70
  text "3" at 5724.84,-1263.5 h70
  text "4" at 8231.51,-1263.5 h70
  text "5" at 10730.5,-1263.5 h70
  text "6" at 13235.5,-1263.5 h70
M10 Fab Notes:
  drawing of 189 lines, arcs and shapes, not listed
  text "DESIGN INFORMATION" at 12382.02,6356.17 h60
  text "MIN. TRACK WIDTH:" at 11737.46,6224.05 h60
  text "8" at 12833.7,6224.05 h60
  text "MIL" at 12988.46,6224.05 h60
  text "MIN. CLEARANCE:" at 11737.46,6099.92 h60
  text "0.2" at 12773.7,6099.93 h60
  text "mm" at 12988.46,6099.92 h60
  text "MIN. VIA PAD SIZE:" at 11737.46,5975.8 h60
  text "24" at 12803.71,5975.8 h60
  text "MIL" at 12988.46,5975.8 h60
  text "0.05mm (2MIL)" at 12432.46,5845.9 h60
  text "MINIMUM ANNULAR RING" at 11408.23,5837.67 h60
  text "EXTERNAL" at 13140.46,5837.67 h60
  text "PER" at 11608.23,5727.55 h60
  text "IPC-D-275 CLASS 2 LEVEL C" at 11828.23,5727.54 h60
  text "MIL, HOLES" at 13316.46,5627.07 h60
  text "+/-" at 12924,5618.48 h60
  text "+/-" at 13778,5618.48 h60
  text "REGISTRATION TOLERANCES:" at 11408.23,5617.42 h60
  text "METAL" at 12608,5617.42 h60
  text "5" at 13184.2,5617.42 h60
  text "3" at 14017.2,5617.42 h60
  text "MIL" at 14133.46,5617.42 h60
  text "HOLE SIZE TOLERANCE (UNLESS OTHERWISE SPECIFIED):" at 11408.23,5519.1 h60
  text "+/-" at 13778,5516.23 h60
  text "3" at 14017.2,5515.17 h60
  text "MIL" at 14133.46,5515.17 h60
  text "MATERIAL:" at 11333.46,5377.52 h60
  text "FR-4 High Tg" at 12319.9,5249 h60
  text "X" at 12175.46,5241.01 h60
  text "FR-408" at 11754.46,5236.49 h60
  text "OTHER" at 13242.46,5236.49 h60
  text "62 MIL (1.6mm) +/-10%" at 12074.56,5093.46 h60
  text "X" at 11954.46,5091.01 h60
  text "THICKNESS:" at 11408.23,5085.24 h60
  text "OTHER" at 13359.46,5085.24 h60
  text "TOLERANCE:" at 11408.23,4946.92 h60
  text "X" at 12256.46,4946.92 h60
  text "ANSI IPC-6012 TYPE 3 CLASS 2" at 12434.48,4946.92 h60
  text "OTHER +/-" at 12434.46,4802.73 h60
  text "BOW & TWIST:" at 11408.23,4657.54 h60
  text "X" at 12256.46,4657.54 h60
  text "ANSI IPC-6012 TYPE 3 CLASS 2" at 12434.48,4657.54 h60
  text "OTHER +/-" at 12434.46,4510.85 h60
  text "DRILLING:" at 11333.46,4380.23 h60
  text "NC_DRILL FILES" at 13094.46,4275.04 h60
  text "REFERENCE:" at 11408.23,4271.1 h60
  text "X" at 12065.46,4271.01 h60
  text "AS SHOWN" at 12243.46,4271.1 h60
  text "X" at 12966.46,4271.1 h60
  text "OTHER" at 13392.46,4128.85 h60
  text "PTH COPPER THICKNESS:" at 11407.91,4125.32 h60
  text "X" at 12547.14,4125.32 h60
  text "20-30 um" at 12675.14,4125.32 h60
  text "BOARD FINISH:" at 11333.46,3977.73 h60
  text "SILKSCREEN:" at 11488.68,3867.6 h60
  text "X" at 12446.46,3867.6 h60
  text "TOP" at 12563.46,3867.6 h60
  text "X" at 12956.46,3867.6 h60
  text "BOTTOM" at 13074.46,3867.6 h60
  text "SILKSCREEN COLOR:" at 11488.68,3712.41 h60
  text "X" at 12445.46,3712.41 h60
  text "WHITE" at 12563.46,3712.41 h60
  text "OTHER" at 13074.46,3712.41 h60
  text "X" at 12576.46,3568.96 h60
  text "GREEN" at 12694.46,3568.96 h60
  text "OTHER" at 13312.46,3568.96 h60
  text "SOLDER RESIST COLOR:" at 11488.68,3562.1 h60
  text "X" at 12576.46,3414.71 h60
  text "MATTE" at 12694.46,3414.71 h60
  text "SEMI-GLOSS" at 13312,3414.07 h60
  text "IMMERSION GOLD (ENIG)" at 12394.46,3241.94 h60
  text "ENEPIG" at 13732,3234.72 h60
  text "SURFACE FINISH:" at 11333.46,3233.72 h60
  text "X" at 12216.46,3233.72 h60
  text "IMM. TIN/SILVER OR EQUIV" at 11663,3096.4 h60
  text "OTHER" at 13094.46,3092.47 h60
  text "ARRAY/PANEL:" at 11333.46,2937.09 h60
  text "CUT AND TRIM PER M1 BOARD OUTLINE" at 12394.46,2928.87 h60
  text "N.C. ROUTE" at 12394.46,2792.9 h60
  text "X" at 13082.46,2792.9 h60
  text "V. SCORE" at 13260.46,2792.9 h60
  text "CERTIFICATION:" at 11333.46,2663.77 h60
  text "MATERIALS AND WORKMANSHIP FOR ALL PCBS" at 12058.46,2663.77 h60
  text "TO MEET OR EXCEED THE REQUIREMENTS OF:" at 12058.46,2569.71 h60
  text "X" at 11695.97,2441.08 h60
  text "ANSI IPC-A-600F CLASS ->" at 11823.96,2441.08 h60
  text "X" at 13471.97,2441.08 h60
  text "2" at 13581.96,2441.08 h60
  text "1" at 13266.96,2439.58 h60
  text "3" at 13935.96,2439.58 h60
  text "X" at 12507.97,2293.39 h60
  text "RoHS" at 12635.96,2293.39 h60
  text "OTHER" at 13280.36,2293.39 h60
  text "PER ORDER" at 13677.42,2293.39 h60
  text "ALL BOARDS MUST MEET OR EXCEED UL94-V0 REQUIREMENTS." at 11361,2139.57 h60
  text "PCB MUST BEAR THE UL94V-0 UL REGISTERED MATERIAL ID NUMBER" at 11361,2023.5 h60
  text "ADDITIONAL REQUIREMENTS:" at 11333.46,1854.08 h60
  text "MICROSECTION:" at 11408.23,1746.95 h60
  text "YES" at 12313.96,1746.95 h60
  text "REQUIRED" at 13175.46,1602.62 h60
  text "BARE BOARD ELEC. TEST:" at 11408.23,1599.76 h60
  text "NONE" at 12713.96,1599.76 h60
  text "X" at 13057.46,1599.76 h60
  text "PER ORDER" at 13767.46,1599.76 h60
  text "XX MIL VIAS REQUIRE NON-CONDUCTIVE FILL AND PLANARIZE" at 11576.38,1394.82 h59
  text "XX MIL VIAS REQUIRE CONDUCTIVE FILL AND PLANARIZE" at 11584.38,1290.84 h60
  text "OUTER XX MIL TRACES REQUIRE 50 OHM SINGLE-ENDED IMPEDANCE" at 11583.39,1127.46 h58
  text "LAYER 2 & 3 (INNER LAYERS) XX MIL WIDE, XX MIL SPACE / TRACES REQUIRE 100 OHM DIFFERENTIAL IMPEDANCE" at 11575.39,891.74 h60
  text ".Layer_Name" at 577,-858.49 h60
M11 Gerber Information:
  lines w10: -292,-930.17 6308,-930.17 ; -292,-726.83 6310,-726.83 ; -292,-523.5 -292,-1133.5 3713,-1133.5 6310,-1133.5 6310,-523.5 -291.5,-523.5 -291.5,-1133.5 1284,-1133.5 ; 2173,-1133.5 2173,-523.5 ; 3440,-726.83 3440,-523.5 ; 4280,-726.83 4280,-523.5 ; 4902,-1140 4902,-937.17
  text "ALL ARTWORK VIEWED FROM TOP SIDE" at -228.5,-655.67 h60
  text "BOARD #:" at 2248,-655.67 h60
  text ".PRJ_Number" at 2793.5,-655.67 h60
  text "REV:" at 3638,-655.67 h60
  text ".PCB_Rev" at 3929.5,-655.67 h60
  text "SVN REV:" at 4476,-655.67 h60
  text ".VersionControl_RevNumber" at 4982,-655.67 h60
  text "LAYER NAME =" at -228.5,-858.49 h60
  text "TID #:" at 2248,-859 h60
  text ".TID" at 2793.5,-859 h60
  text "PLOT NAME =" at -228.5,-1064.34 h60
  text ".plot_File_Name" at 577,-1064.34 h60
  text "GENERATED    :" at 2250,-1064.34 h60
  text ".Print_Date" at 3119.5,-1064.34 h60
  text ".Print_Time" at 3848.5,-1064.34 h60
  text "TEXAS INSTRUMENTS" at 5113,-1064.34 h60
M12 Stackup:
  text ".Layer_Name" at 577,-858.49 h60
M13 Component Bodies Top:
  text ".Layer_Name" at 577,-858.49 h60
M14 Component Bodies Bottom:
  text ".Layer_Name" at 577,-858.49 h60
M15 Courtyards Top:
  text ".Layer_Name" at 577,-858.49 h60
M16 Courtyards Bottom:
  text ".Layer_Name" at 577,-858.49 h60
Drill Drawing:
  circle w10: c5595.44,4509.34 r27.59
  lines w10: 5567.85,3985.04 5623.04,3985.04 5623.04,4040.23 5567.85,4040.23 5567.85,3985.04 ; 5567.85,4123.02 5581.64,4123.02 5595.44,4109.22 5609.24,4123.02 5623.04,4123.02 5609.24,4136.82 5623.04,4150.61 5609.24,4150.61 5595.44,4164.41 5581.64,4150.61 5567.85,4150.61 5581.64,4136.82 5567.85,4123.02 ; 5567.85,4233.4 5595.44,4247.19 5623.04,4233.4 5609.24,4260.99 5623.04,4288.59 5595.44,4274.79 5567.85,4288.59 5581.64,4260.99 5567.85,4233.4 ; 5567.85,4412.76 5623.04,4412.76 5595.44,4357.57 5567.85,4412.76 ; 5567.85,4619.72 5581.64,4619.72 5581.64,4605.92 5609.24,4605.92 5609.24,4619.72 5623.04,4619.72 5623.04,4647.32 5609.24,4647.32 5609.24,4661.11 5581.64,4661.11 5581.64,4647.32 5567.85,4647.32 5567.85,4619.72
  lines w12: 5517.81,3947.79 8748.33,3947.79 ; 5517.81,4692.85 8748.33,4692.85 ; 5855.67,3823.62 5855.67,4817.02 ; 6187.68,3823.62 6187.68,4817.02 ; 6824.23,3823.62 6824.23,4817.02 ; 7083.34,3823.62 7083.34,4817.02 ; 7458.49,3823.62 7458.49,4817.02 ; 8181.87,3823.62 8181.87,4817.02 ; 5517.81,3823.62 8748.33,3823.62 8748.33,4817.02 5517.81,4817.02 5517.81,3823.62
  text "Symbol" at 5592.32,4730.1 h72
  text "Quantity" at 5892.92,4730.1 h72
  text "Finished Hole Size" at 6224.93,4730.1 h72
  text "Plated" at 6861.48,4730.1 h72
  text "Hole Type" at 7120.59,4730.1 h72
  text "Drill Layer Pair" at 7495.74,4730.1 h72
  text "Hole Tolerance" at 8219.13,4730.1 h72
  text "5" at 5892.92,4605.92 h60
  text "7.87mil (0.200mm)" at 6224.93,4605.92 h60
  text "PTH" at 6861.48,4605.92 h60
  text "Round" at 7120.59,4605.92 h60
  text "Top Layer - Bottom Layer" at 7495.74,4605.92 h60
  text "207" at 5892.92,4481.75 h60
  text "10.00mil (0.254mm)" at 6224.93,4481.75 h60
  text "PTH" at 6861.48,4481.75 h60
  text "Round" at 7120.59,4481.75 h60
  text "Top Layer - Bottom Layer" at 7495.74,4481.75 h60
  text "28" at 5892.92,4357.57 h60
  text "33.47mil (0.850mm)" at 6224.93,4357.57 h60
  text "PTH" at 6861.48,4357.57 h60
  text "Round" at 7120.59,4357.57 h60
  text "Top Layer - Bottom Layer" at 7495.74,4357.57 h60
  text "4" at 5892.92,4233.4 h60
  text "40.00mil (1.016mm)" at 6224.93,4233.4 h60
  text "PTH" at 6861.48,4233.4 h60
  text "Round" at 7120.59,4233.4 h60
  text "Top Layer - Bottom Layer" at 7495.74,4233.4 h60
  text "8" at 5892.92,4109.22 h60
  text "51.18mil (1.300mm)" at 6224.93,4109.22 h60
  text "PTH" at 6861.48,4109.22 h60
  text "Round" at 7120.59,4109.22 h60
  text "Top Layer - Bottom Layer" at 7495.74,4109.22 h60
  text "21" at 5892.92,3985.04 h60
  text "63.00mil (1.600mm)" at 6224.93,3985.04 h60
  text "PTH" at 6861.48,3985.04 h60
  text "Round" at 7120.59,3985.04 h60
  text "Top Layer - Bottom Layer" at 7495.74,3985.04 h60
  text "273 Total" at 5892.92,3860.87 h60
  text ".Layer_Name" at 577,-858.49 h60
M17 Embedded Cavity:
  text ".Layer_Name" at 577,-858.49 h60
M18 Embedded Assembly:
  text ".Layer_Name" at 577,-858.49 h60
M19 Embedded Keepout:
  text ".Layer_Name" at 577,-858.49 h60

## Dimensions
1116.02,688.98 to 2176.63,736.22 on Top Overlay
2574.8,2000.85 to 2515.75,798.28 on Top Overlay
3299.21,0 to 3913.39,2763.78 on Top Overlay
0,-400 to 1000,-400 on M2 Board Dimensions
0,0 to 0,2751.97 on M2 Board Dimensions
0,0 to 3299.21,0 on M2 Board Dimensions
